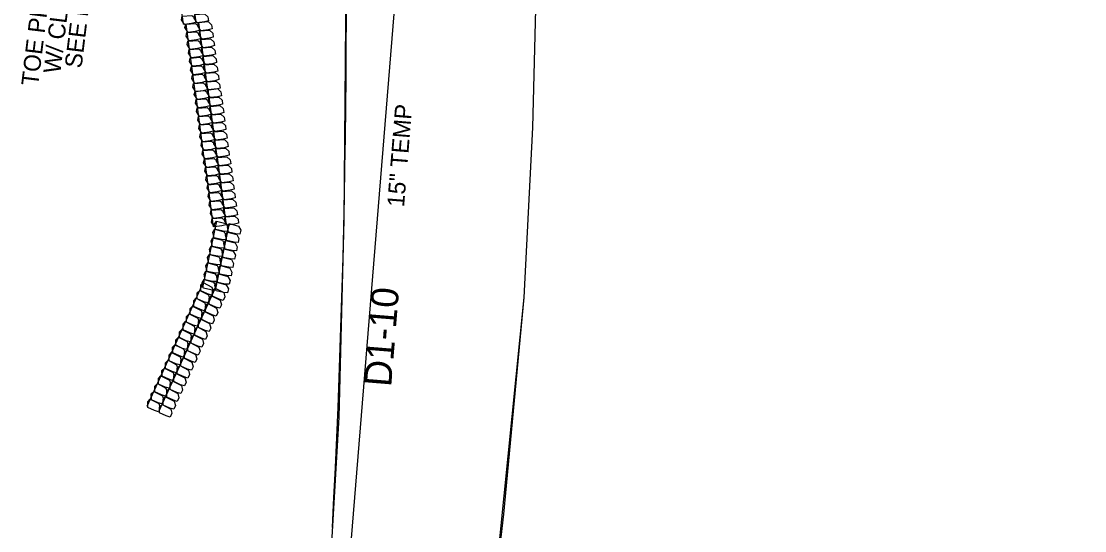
# Model space of a CAD drawing. Extents: x 465700 to 483515, y 488970 to 507540.
# Drawn here: x 481262.3 to 481574.3, y 491204.6 to 491354.2 of the extents above; entities that cross this region are included whole.
import ezdxf

# ---------------------------------------------------------------- set-up
doc = ezdxf.new("R2010")
doc.units = 0
for name, color, linetype in [('Default', 7, 'Continuous'), ('Exist Plan Preparation Watershed Blue', 7, 'Continuous'), ('Prop Drainage Structure Pipe RCP 15in Class III', 7, 'Continuous'), ('Prop Drainage Structure Pipe RCP 15in Class III Label', 7, 'Continuous'), ('Prop Erosion Embankment Toe Protection CELL', 7, 'Continuous'), ('Prop Erosion Embankment Toe Protection Label', 7, 'Continuous'), ('Scratch_Level_8', 7, 'Continuous')]:
    doc.layers.add(name, color=color, linetype=linetype)

msp = doc.modelspace()

# ---------------------------------------------------------------- linework, layer by layer
at = {"layer": 'Default'}
msp.add_arc((478448.2, 491360.26), 2909.5, 356.95228, 8.055, dxfattribs=at)
at = {"layer": 'Exist Plan Preparation Watershed Blue'}
for points in [[(482127.99, 491863.91), (481786.78, 491759.9), (481568.07, 491531.08), (481568.07, 491531.08), (481568.07, 491531.08), (481568.07, 491531.08), (481568.07, 491531.08), (481489.54, 491524.26), (481441, 491522.17), (481407.45, 491514.97), (481410.05, 491479.29), (481411.52, 491442.54), (481412.58, 491412.05), (481413.67, 491377.22), (481412.27, 491323.04), (481409.74, 491273.14), (481403.82, 491209.49), (481400.35, 491179.93)], [(481351.25, 491164.11), (481355.63, 491237.92), (481357.02, 491295.88), (481357.71, 491377.55), (481356.61, 491435.42), (481354.34, 491495.85), (481349.13, 491584.55), (481341.19, 491673.05), (481328.95, 491769.45), (481331.36, 491785.24), (481338.28, 491786.26), (481358.32, 491790.73), (481372.6, 491727.76), (481383.56, 491677.38), (481390.7, 491636.27), (481400.08, 491578.77), (481407.45, 491514.97), (481410.05, 491479.29), (481411.52, 491442.54), (481412.58, 491412.05), (481413.67, 491377.22), (481412.27, 491323.04), (481409.74, 491273.14), (481400.35, 491179.93)]]:
    msp.add_lwpolyline(points, dxfattribs=at)
at = {"layer": 'Prop Drainage Structure Pipe RCP 15in Class III'}
msp.add_line((481349.75, 491085.88), (481375.95, 491408.81), dxfattribs=at)
at = {"layer": 'Prop Erosion Embankment Toe Protection CELL'}
for p, q in [((481307.2, 491373.17), (481309.82, 491353.34)), ((481310.96, 491373.67), (481313.58, 491353.84)), ((481310.58, 491353.38), (481313.2, 491333.56)), ((481314.35, 491353.88), (481316.97, 491334.05)), ((481313.31, 491333.72), (481315.93, 491313.89)), ((481317.08, 491334.22), (481319.7, 491314.39)), ((481319.82, 491314.21), (481322.44, 491294.38)), ((481316.05, 491313.71), (481318.67, 491293.88)), ((481319.61, 491295.56), (481315.49, 491275.99)), ((481323.33, 491294.78), (481319.21, 491275.21)), ((481315.73, 491277.46), (481307.43, 491259.26)), ((481319.18, 491275.88), (481310.89, 491257.68)), ((481307.47, 491259.24), (481299.17, 491241.04)), ((481310.93, 491257.67), (481302.63, 491239.47))]:
    msp.add_line(p, q, dxfattribs=at)
for points in [[(481313.48, 491353.88), (481312.31, 491353.57), (481310.18, 491353.29), (481309.29, 491354.68), (481309.5, 491355.72), (481312.35, 491355.95), (481313.32, 491355.07), (481313.48, 491353.88)], [(481317.25, 491354.37), (481316.08, 491354.07), (481313.94, 491353.79), (481313.05, 491355.18), (481313.27, 491356.22), (481316.11, 491356.44), (481317.09, 491355.56), (481317.25, 491354.37)], [(481314.56, 491351.54), (481313.39, 491351.23), (481311.25, 491350.95), (481310.36, 491352.35), (481310.58, 491353.38), (481313.42, 491353.61), (481314.4, 491352.7), (481314.56, 491351.54)], [(481318.32, 491352.04), (481317.15, 491351.73), (481315.02, 491351.45), (481314.13, 491352.84), (481314.35, 491353.88), (481317.19, 491354.11), (481318.17, 491353.2), (481318.32, 491352.04)], [(481318.65, 491349.56), (481317.48, 491349.23), (481315.35, 491348.95), (481314.46, 491350.37), (481314.67, 491351.4), (481317.52, 491351.6), (481318.5, 491350.7), (481318.65, 491349.56)], [(481314.88, 491349.06), (481313.72, 491348.73), (481311.58, 491348.45), (481310.69, 491349.87), (481310.91, 491350.91), (481313.76, 491351.11), (481314.73, 491350.2), (481314.88, 491349.06)], [(481315.21, 491346.56), (481314.05, 491346.23), (481311.92, 491345.94), (481311.02, 491347.36), (481311.24, 491348.4), (481314.09, 491348.6), (481315.06, 491347.72), (481315.21, 491346.56)], [(481318.98, 491347.06), (481317.81, 491346.72), (481315.68, 491346.44), (481314.79, 491347.86), (481315.01, 491348.9), (481317.85, 491349.1), (481318.83, 491348.22), (481318.98, 491347.06)], [(481315.55, 491344.05), (481314.38, 491343.75), (481312.24, 491343.47), (481311.35, 491344.86), (481311.57, 491345.9), (481314.41, 491346.12), (481315.39, 491345.24), (481315.55, 491344.05)], [(481319.31, 491344.55), (481318.14, 491344.25), (481316.01, 491343.96), (481315.12, 491345.36), (481315.34, 491346.4), (481318.18, 491346.62), (481319.15, 491345.74), (481319.31, 491344.55)], [(481315.87, 491341.58), (481314.7, 491341.27), (481312.57, 491340.99), (481311.68, 491342.38), (481311.9, 491343.42), (481314.74, 491343.65), (481315.72, 491342.74), (481315.87, 491341.58)], [(481319.64, 491342.07), (481318.47, 491341.77), (481316.34, 491341.49), (481315.45, 491342.88), (481315.66, 491343.92), (481318.51, 491344.14), (481319.49, 491343.24), (481319.64, 491342.07)], [(481316.2, 491339.1), (481315.03, 491338.77), (481312.9, 491338.48), (481312.01, 491339.9), (481312.22, 491340.94), (481315.07, 491341.14), (481316.05, 491340.24), (481316.2, 491339.1)], [(481319.97, 491339.6), (481318.8, 491339.26), (481316.67, 491338.98), (481315.78, 491340.4), (481315.99, 491341.44), (481318.84, 491341.64), (481319.82, 491340.74), (481319.97, 491339.6)], [(481320.3, 491337.09), (481319.13, 491336.76), (481317, 491336.48), (481316.11, 491337.9), (481316.32, 491338.94), (481319.17, 491339.14), (481320.14, 491338.26), (481320.3, 491337.09)], [(481316.53, 491336.59), (481315.36, 491336.26), (481313.23, 491335.98), (481312.34, 491337.4), (481312.56, 491338.44), (481315.4, 491338.64), (481316.38, 491337.76), (481316.53, 491336.59)], [(481316.86, 491334.09), (481315.69, 491333.79), (481313.56, 491333.5), (481312.67, 491334.9), (481312.89, 491335.94), (481315.73, 491336.16), (481316.71, 491335.28), (481316.86, 491334.09)], [(481320.63, 491334.59), (481319.46, 491334.28), (481317.33, 491334), (481316.44, 491335.4), (481316.65, 491336.43), (481319.5, 491336.66), (481320.47, 491335.78), (481320.63, 491334.59)], [(481317.28, 491331.88), (481316.11, 491331.57), (481313.98, 491331.29), (481313.09, 491332.68), (481313.31, 491333.72), (481316.15, 491333.94), (481317.13, 491333.04), (481317.28, 491331.88)], [(481321.05, 491332.37), (481319.88, 491332.07), (481317.75, 491331.79), (481316.86, 491333.18), (481317.08, 491334.22), (481319.92, 491334.44), (481320.9, 491333.54), (481321.05, 491332.37)], [(481317.61, 491329.4), (481316.45, 491329.07), (481314.31, 491328.78), (481313.42, 491330.2), (481313.64, 491331.24), (481316.48, 491331.44), (481317.46, 491330.54), (481317.61, 491329.4)], [(481321.38, 491329.89), (481320.21, 491329.56), (481318.08, 491329.28), (481317.19, 491330.7), (481317.4, 491331.74), (481320.25, 491331.94), (481321.23, 491331.03), (481321.38, 491329.89)], [(481321.71, 491327.39), (481320.54, 491327.06), (481318.41, 491326.78), (481317.52, 491328.2), (481317.73, 491329.24), (481320.58, 491329.44), (481321.56, 491328.56), (481321.71, 491327.39)], [(481317.94, 491326.89), (481316.78, 491326.56), (481314.64, 491326.28), (481313.75, 491327.7), (481313.97, 491328.74), (481316.82, 491328.94), (481317.79, 491328.06), (481317.94, 491326.89)], [(481318.27, 491324.39), (481317.1, 491324.08), (481314.97, 491323.8), (481314.08, 491325.2), (481314.3, 491326.23), (481317.14, 491326.46), (481318.12, 491325.58), (481318.27, 491324.39)], [(481322.04, 491324.89), (481320.87, 491324.58), (481318.74, 491324.3), (481317.85, 491325.7), (481318.07, 491326.73), (481320.91, 491326.96), (481321.88, 491326.08), (481322.04, 491324.89)], [(481318.6, 491321.91), (481317.43, 491321.61), (481315.3, 491321.32), (481314.41, 491322.72), (481314.63, 491323.76), (481317.47, 491323.98), (481318.45, 491323.08), (481318.6, 491321.91)], [(481322.37, 491322.41), (481321.2, 491322.1), (481319.07, 491321.82), (481318.18, 491323.22), (481318.39, 491324.25), (481321.24, 491324.48), (481322.21, 491323.57), (481322.37, 491322.41)], [(481318.93, 491319.43), (481317.76, 491319.1), (481315.63, 491318.82), (481314.74, 491320.24), (481314.95, 491321.28), (481317.8, 491321.48), (481318.78, 491320.57), (481318.93, 491319.43)], [(481322.7, 491319.93), (481321.53, 491319.6), (481319.4, 491319.32), (481318.5, 491320.74), (481318.72, 491321.78), (481321.57, 491321.98), (481322.55, 491321.07), (481322.7, 491319.93)], [(481319.26, 491316.93), (481318.09, 491316.6), (481315.96, 491316.32), (481315.07, 491317.74), (481315.28, 491318.77), (481318.13, 491318.98), (481319.11, 491318.1), (481319.26, 491316.93)], [(481323.03, 491317.43), (481321.86, 491317.1), (481319.73, 491316.82), (481318.84, 491318.24), (481319.05, 491319.27), (481321.9, 491319.47), (481322.87, 491318.59), (481323.03, 491317.43)], [(481323.36, 491314.93), (481322.19, 491314.62), (481320.06, 491314.34), (481319.17, 491315.73), (481319.38, 491316.77), (481322.23, 491316.99), (481323.2, 491316.11), (481323.36, 491314.93)], [(481319.59, 491314.43), (481318.42, 491314.12), (481316.29, 491313.84), (481315.4, 491315.23), (481315.62, 491316.27), (481318.46, 491316.5), (481319.43, 491315.62), (481319.59, 491314.43)], [(481320.02, 491311.87), (481318.85, 491311.56), (481316.72, 491311.28), (481315.83, 491312.67), (481316.05, 491313.71), (481318.89, 491313.94), (481319.87, 491313.03), (481320.02, 491311.87)], [(481323.79, 491312.37), (481322.62, 491312.06), (481320.49, 491311.78), (481319.6, 491313.17), (481319.82, 491314.21), (481322.66, 491314.44), (481323.64, 491313.53), (481323.79, 491312.37)], [(481320.35, 491309.39), (481319.19, 491309.06), (481317.05, 491308.78), (481316.16, 491310.2), (481316.38, 491311.23), (481319.22, 491311.43), (481320.2, 491310.53), (481320.35, 491309.39)], [(481324.12, 491309.89), (481322.95, 491309.56), (481320.82, 491309.27), (481319.93, 491310.69), (481320.14, 491311.73), (481322.99, 491311.93), (481323.97, 491311.03), (481324.12, 491309.89)], [(481320.68, 491306.89), (481319.52, 491306.55), (481317.38, 491306.27), (481316.49, 491307.69), (481316.71, 491308.73), (481319.56, 491308.93), (481320.53, 491308.05), (481320.68, 491306.89)], [(481324.45, 491307.38), (481323.28, 491307.05), (481321.15, 491306.77), (481320.26, 491308.19), (481320.47, 491309.23), (481323.32, 491309.43), (481324.3, 491308.55), (481324.45, 491307.38)], [(481321.01, 491304.38), (481319.84, 491304.08), (481317.71, 491303.79), (481316.82, 491305.19), (481317.04, 491306.23), (481319.88, 491306.45), (481320.86, 491305.57), (481321.01, 491304.38)], [(481324.78, 491304.88), (481323.61, 491304.57), (481321.48, 491304.29), (481320.59, 491305.69), (481320.8, 491306.73), (481323.65, 491306.95), (481324.62, 491306.07), (481324.78, 491304.88)], [(481325.11, 491302.4), (481323.94, 491302.1), (481321.81, 491301.81), (481320.92, 491303.21), (481321.13, 491304.25), (481323.98, 491304.47), (481324.95, 491303.57), (481325.11, 491302.4)], [(481321.34, 491301.9), (481320.17, 491301.6), (481318.04, 491301.32), (481317.15, 491302.71), (481317.37, 491303.75), (481320.21, 491303.97), (481321.19, 491303.07), (481321.34, 491301.9)], [(481321.67, 491299.43), (481320.5, 491299.09), (481318.37, 491298.81), (481317.48, 491300.23), (481317.69, 491301.27), (481320.54, 491301.47), (481321.52, 491300.57), (481321.67, 491299.43)], [(481325.44, 491299.92), (481324.27, 491299.59), (481322.14, 491299.31), (481321.24, 491300.73), (481321.46, 491301.77), (481324.31, 491301.97), (481325.29, 491301.06), (481325.44, 491299.92)], [(481322, 491296.92), (481320.83, 491296.59), (481318.7, 491296.31), (481317.81, 491297.73), (481318.02, 491298.77), (481320.87, 491298.97), (481321.85, 491298.09), (481322, 491296.92)], [(481325.77, 491297.42), (481324.6, 491297.09), (481322.47, 491296.81), (481321.58, 491298.23), (481321.79, 491299.27), (481324.64, 491299.47), (481325.61, 491298.59), (481325.77, 491297.42)], [(481322.33, 491294.42), (481321.16, 491294.11), (481319.03, 491293.83), (481318.14, 491295.23), (481318.36, 491296.26), (481321.2, 491296.49), (481322.17, 491295.61), (481322.33, 491294.42)], [(481322.74, 491292.5), (481321.54, 491292.6), (481319.43, 491293.05), (481319.06, 491294.66), (481319.61, 491295.56), (481322.36, 491294.83), (481322.99, 491293.65), (481322.74, 491292.5)], [(481326.1, 491294.92), (481324.93, 491294.61), (481322.8, 491294.33), (481321.91, 491295.72), (481322.12, 491296.76), (481324.97, 491296.99), (481325.94, 491296.11), (481326.1, 491294.92)], [(481322.23, 491290.06), (481321.02, 491290.13), (481318.91, 491290.57), (481318.54, 491292.21), (481319.09, 491293.12), (481321.84, 491292.36), (481322.47, 491291.18), (481322.23, 491290.06)], [(481325.95, 491289.27), (481324.74, 491289.35), (481322.63, 491289.79), (481322.26, 491291.43), (481322.81, 491292.33), (481325.56, 491291.58), (481326.18, 491290.4), (481325.95, 491289.27)], [(481326.46, 491291.72), (481325.26, 491291.82), (481323.15, 491292.26), (481322.78, 491293.87), (481323.33, 491294.78), (481326.08, 491294.05), (481326.7, 491292.87), (481326.46, 491291.72)], [(481321.71, 491287.59), (481320.5, 491287.66), (481318.39, 491288.1), (481318.02, 491289.74), (481318.57, 491290.65), (481321.32, 491289.89), (481321.95, 491288.73), (481321.71, 491287.59)], [(481325.43, 491286.8), (481324.22, 491286.88), (481322.11, 491287.32), (481321.74, 491288.96), (481322.29, 491289.86), (481325.04, 491289.11), (481325.67, 491287.95), (481325.43, 491286.8)], [(481320.67, 491282.67), (481319.47, 491282.77), (481317.36, 491283.21), (481316.99, 491284.82), (481317.54, 491285.73), (481320.29, 491285), (481320.91, 491283.82), (481320.67, 491282.67)], [(481321.19, 491285.11), (481319.98, 491285.21), (481317.88, 491285.66), (481317.5, 491287.27), (481318.05, 491288.18), (481320.81, 491287.44), (481321.44, 491286.29), (481321.19, 491285.11)], [(481324.91, 491284.33), (481323.7, 491284.43), (481321.6, 491284.87), (481321.22, 491286.49), (481321.77, 491287.39), (481324.53, 491286.66), (481325.15, 491285.51), (481324.91, 491284.33)], [(481320.16, 491280.22), (481318.95, 491280.3), (481316.84, 491280.74), (481316.47, 491282.38), (481317.02, 491283.28), (481319.77, 491282.53), (481320.39, 491281.35), (481320.16, 491280.22)], [(481324.39, 491281.89), (481323.19, 491281.99), (481321.08, 491282.43), (481320.71, 491284.04), (481321.25, 491284.95), (481324.01, 491284.21), (481324.63, 491283.03), (481324.39, 491281.89)], [(481319.64, 491277.75), (481318.43, 491277.83), (481316.32, 491278.27), (481315.95, 491279.91), (481316.5, 491280.81), (481319.25, 491280.05), (481319.88, 491278.9), (481319.64, 491277.75)], [(481323.36, 491276.97), (481322.15, 491277.04), (481320.04, 491277.49), (481319.67, 491279.12), (481320.22, 491280.03), (481322.97, 491279.27), (481323.6, 491278.12), (481323.36, 491276.97)], [(481323.88, 491279.44), (481322.67, 491279.51), (481320.56, 491279.96), (481320.19, 491281.59), (481320.74, 491282.5), (481323.49, 491281.74), (481324.11, 491280.56), (481323.88, 491279.44)], [(481318.12, 491273.79), (481316.96, 491274.15), (481315.01, 491275.04), (481314.99, 491276.69), (481315.73, 491277.46), (481318.26, 491276.14), (481318.61, 491274.85), (481318.12, 491273.79)], [(481319.12, 491275.28), (481317.91, 491275.38), (481315.81, 491275.82), (481315.43, 491277.44), (481315.98, 491278.34), (481318.74, 491277.61), (481319.36, 491276.45), (481319.12, 491275.28)], [(481322.84, 491274.5), (481321.63, 491274.6), (481319.53, 491275.04), (481319.15, 491276.65), (481319.7, 491277.56), (481322.46, 491276.83), (481323.08, 491275.67), (481322.84, 491274.5)], [(481317.08, 491271.51), (481315.92, 491271.85), (481313.96, 491272.74), (481313.96, 491274.42), (481314.69, 491275.18), (481317.21, 491273.84), (481317.56, 491272.56), (481317.08, 491271.51)], [(481320.54, 491269.93), (481319.37, 491270.27), (481317.42, 491271.16), (481317.41, 491272.84), (481318.15, 491273.61), (481320.67, 491272.27), (481321.02, 491270.98), (481320.54, 491269.93)], [(481321.58, 491272.21), (481320.42, 491272.57), (481318.46, 491273.46), (481318.45, 491275.12), (481319.18, 491275.88), (481321.71, 491274.56), (481322.06, 491273.28), (481321.58, 491272.21)], [(481314.99, 491266.92), (481313.83, 491267.28), (481311.88, 491268.17), (481311.86, 491269.82), (481312.59, 491270.59), (481315.13, 491269.27), (481315.48, 491268.01), (481314.99, 491266.92)], [(481316.03, 491269.21), (481314.87, 491269.55), (481312.91, 491270.44), (481312.91, 491272.12), (481313.64, 491272.89), (481316.16, 491271.54), (481316.52, 491270.28), (481316.03, 491269.21)], [(481319.49, 491267.64), (481318.33, 491267.98), (481316.37, 491268.87), (481316.37, 491270.54), (481317.1, 491271.31), (481319.62, 491269.97), (481319.98, 491268.71), (481319.49, 491267.64)], [(481313.95, 491264.64), (481312.79, 491265), (481310.84, 491265.89), (481310.82, 491267.55), (481311.56, 491268.31), (481314.09, 491266.99), (481314.44, 491265.71), (481313.95, 491264.64)], [(481318.44, 491265.34), (481317.29, 491265.7), (481315.33, 491266.59), (481315.32, 491268.25), (481316.05, 491269.01), (481318.58, 491267.69), (481318.94, 491266.43), (481318.44, 491265.34)], [(481312.91, 491262.37), (481311.75, 491262.7), (481309.79, 491263.6), (481309.79, 491265.27), (481310.52, 491266.04), (481313.04, 491264.7), (481313.39, 491263.41), (481312.91, 491262.37)], [(481316.37, 491260.79), (481315.21, 491261.13), (481313.25, 491262.02), (481313.24, 491263.7), (481313.98, 491264.46), (481316.5, 491263.12), (481316.85, 491261.84), (481316.37, 491260.79)], [(481317.41, 491263.06), (481316.25, 491263.43), (481314.3, 491264.32), (481314.28, 491265.97), (481315.01, 491266.74), (481317.55, 491265.42), (481317.89, 491264.13), (481317.41, 491263.06)], [(481310.82, 491257.77), (481309.66, 491258.13), (481307.71, 491259.02), (481307.69, 491260.68), (481308.43, 491261.44), (481310.96, 491260.13), (481311.31, 491258.86), (481310.82, 491257.77)], [(481311.86, 491260.07), (481310.7, 491260.41), (481308.74, 491261.3), (481308.74, 491262.98), (481309.47, 491263.74), (481311.99, 491262.4), (481312.35, 491261.14), (481311.86, 491260.07)], [(481315.32, 491258.49), (481314.16, 491258.83), (481312.2, 491259.72), (481312.2, 491261.4), (481312.93, 491262.17), (481315.45, 491260.82), (481315.81, 491259.56), (481315.32, 491258.49)], [(481309.86, 491255.57), (481308.71, 491255.93), (481306.75, 491256.82), (481306.74, 491258.48), (481307.47, 491259.24), (481310, 491257.92), (481310.35, 491256.64), (481309.86, 491255.57)], [(481313.32, 491253.99), (481312.17, 491254.35), (481310.21, 491255.25), (481310.19, 491256.9), (481310.93, 491257.67), (481313.46, 491256.35), (481313.81, 491255.06), (481313.32, 491253.99)], [(481314.27, 491256.19), (481313.12, 491256.56), (481311.16, 491257.45), (481311.15, 491259.1), (481311.88, 491259.87), (481314.41, 491258.55), (481314.77, 491257.29), (481314.27, 491256.19)], [(481307.78, 491251), (481306.61, 491251.33), (481304.66, 491252.23), (481304.65, 491253.9), (481305.39, 491254.67), (481307.91, 491253.33), (481308.26, 491252.07), (481307.78, 491251)], [(481308.82, 491253.29), (481307.66, 491253.63), (481305.7, 491254.52), (481305.7, 491256.2), (481306.43, 491256.97), (481308.95, 491255.63), (481309.3, 491254.34), (481308.82, 491253.29)], [(481312.28, 491251.72), (481311.12, 491252.06), (481309.16, 491252.95), (481309.16, 491254.63), (481309.89, 491255.39), (481312.41, 491254.05), (481312.76, 491252.76), (481312.28, 491251.72)], [(481306.73, 491248.7), (481305.58, 491249.06), (481303.62, 491249.95), (481303.61, 491251.61), (481304.34, 491252.37), (481306.87, 491251.05), (481307.23, 491249.79), (481306.73, 491248.7)], [(481311.24, 491249.42), (481310.07, 491249.76), (481308.11, 491250.65), (481308.11, 491252.33), (481308.84, 491253.09), (481311.36, 491251.75), (481311.72, 491250.49), (481311.24, 491249.42)], [(481305.69, 491246.42), (481304.54, 491246.79), (481302.58, 491247.68), (481302.57, 491249.33), (481303.3, 491250.1), (481305.83, 491248.78), (481306.18, 491247.49), (481305.69, 491246.42)], [(481309.15, 491244.85), (481308, 491245.21), (481306.04, 491246.1), (481306.03, 491247.76), (481306.76, 491248.52), (481309.29, 491247.2), (481309.64, 491245.92), (481309.15, 491244.85)], [(481310.19, 491247.12), (481309.03, 491247.48), (481307.08, 491248.38), (481307.06, 491250.03), (481307.8, 491250.8), (481310.33, 491249.48), (481310.69, 491248.21), (481310.19, 491247.12)], [(481303.61, 491241.85), (481302.44, 491242.19), (481300.49, 491243.08), (481300.48, 491244.76), (481301.22, 491245.52), (481303.74, 491244.18), (481304.1, 491242.92), (481303.61, 491241.85)], [(481304.66, 491244.15), (481303.49, 491244.49), (481301.54, 491245.38), (481301.53, 491247.06), (481302.26, 491247.82), (481304.78, 491246.48), (481305.13, 491245.2), (481304.66, 491244.15)], [(481308.11, 491242.57), (481306.95, 491242.91), (481304.99, 491243.8), (481304.99, 491245.48), (481305.72, 491246.25), (481308.24, 491244.9), (481308.59, 491243.62), (481308.11, 491242.57)], [(481302.56, 491239.55), (481301.41, 491239.92), (481299.45, 491240.81), (481299.44, 491242.46), (481300.17, 491243.23), (481302.7, 491241.91), (481303.06, 491240.65), (481302.56, 491239.55)], [(481307.07, 491240.28), (481305.9, 491240.61), (481303.95, 491241.51), (481303.94, 491243.18), (481304.67, 491243.95), (481307.2, 491242.61), (481307.55, 491241.34), (481307.07, 491240.28)], [(481306.02, 491237.98), (481304.86, 491238.34), (481302.91, 491239.23), (481302.89, 491240.89), (481303.63, 491241.65), (481306.16, 491240.33), (481306.52, 491239.07), (481306.02, 491237.98)]]:
    msp.add_lwpolyline(points, dxfattribs=at)
at = {"layer": 'Scratch_Level_8'}
msp.add_line((481349.75, 491085.88), (481375.95, 491408.81), dxfattribs=at)

# ---------------------------------------------------------------- texts
at = {"layer": 'Prop Drainage Structure Pipe RCP 15in Class III Label'}
msp.add_text('15" TEMP', height=5, rotation=85.3616, dxfattribs=at).set_placement((481374.61, 491299.52))
at = {"layer": 'Prop Erosion Embankment Toe Protection Label'}
for s, p in [('TOE PROTECTION', (481267.27, 491335.03)), ('W/ CL B RIPRAP', (481273.76, 491338.68)), ('SEE DETAIL H', (481280, 491340.26))]:
    msp.add_text(s, height=5, rotation=83.0365, dxfattribs=at).set_placement(p)
at = {"layer": 'Scratch_Level_8'}
msp.add_text('D1-10', height=8, rotation=85.3616, dxfattribs=at).set_placement((481370.83, 491246.7))

doc.saveas('drawing.dxf')
